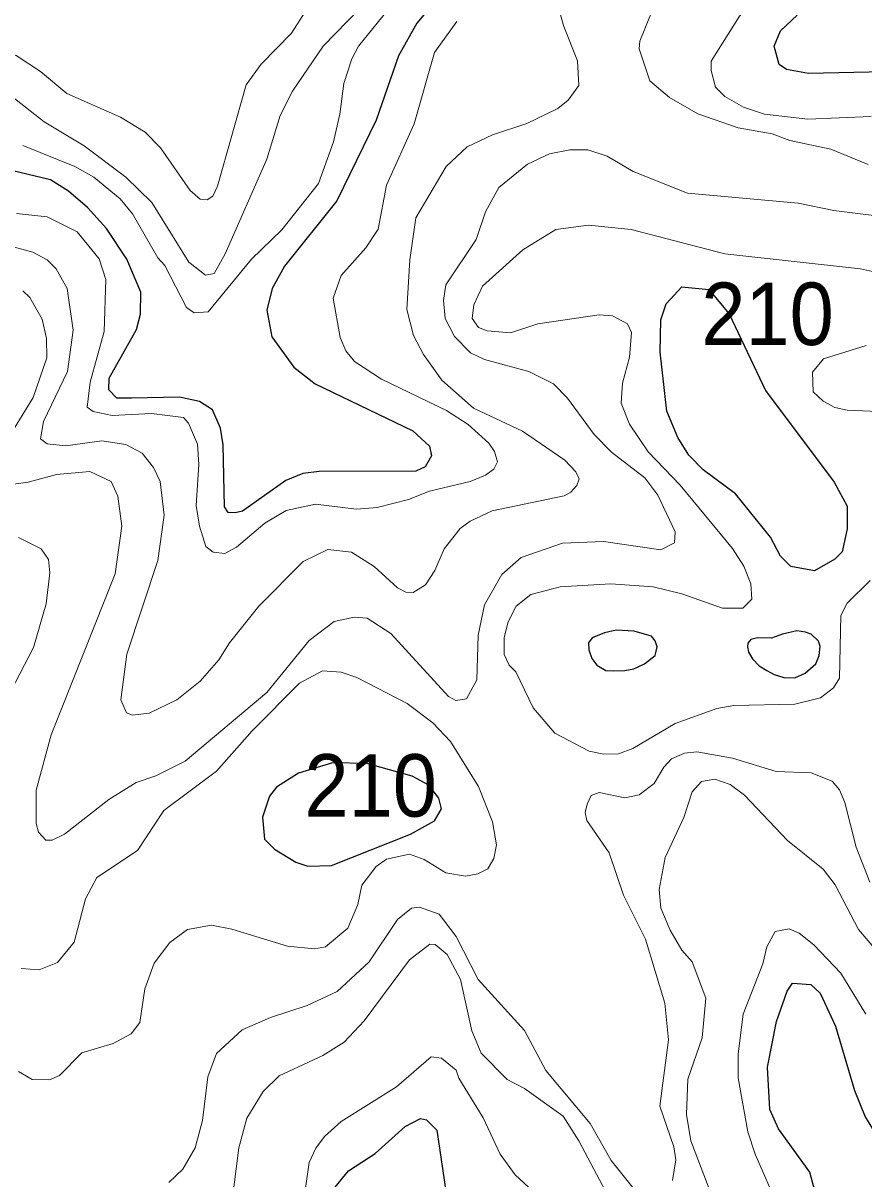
# Model space of a CAD drawing. Extents: x 673.6 to 698.9, y 7012 to 7040.1.
# Drawn here: x 694.799 to 695.876, y 7018.541 to 7020.022 of the extents above; entities that cross this region are included whole.
import ezdxf

# ---------------------------------------------------------------- set-up
doc = ezdxf.new("R2010")
doc.units = 0
doc.header["$LTSCALE"] = 0.032
doc.layers.add('1', color=7, linetype='Continuous', lineweight=25)
doc.layers.add('2', color=7, linetype='Continuous', lineweight=13)
doc.layers.add('21', color=7, linetype='Continuous')

msp = doc.modelspace()

# ---------------------------------------------------------------- linework, layer by layer
at = {"layer": '1'}
for points in [[(695.3336, 7020.0584), (695.3035, 7020.0216), (695.28, 7019.9796), (695.2513, 7019.8974), (695.2012, 7019.7939), (695.1342, 7019.7102), (695.1181, 7019.6817), (695.1115, 7019.654), (695.1177, 7019.6201), (695.1462, 7019.5812), (695.1734, 7019.5599), (695.2985, 7019.4995), (695.3197, 7019.48), (695.3223, 7019.4673), (695.3142, 7019.4535), (695.3024, 7019.448), (695.1784, 7019.4475), (695.1576, 7019.445), (695.1358, 7019.4358), (695.0801, 7019.3967), (695.0707, 7019.3943), (695.0619, 7019.3949), (695.0572, 7019.4023), (695.0555, 7019.4816), (695.0521, 7019.503), (695.042, 7019.5266), (695.0251, 7019.5371), (694.9997, 7019.5428), (694.9381, 7019.5412), (694.9192, 7019.5415), (694.9093, 7019.5522), (694.9094, 7019.5668), (694.9447, 7019.6295), (694.9495, 7019.6488), (694.9502, 7019.6769), (694.9323, 7019.7195), (694.9063, 7019.7586), (694.8819, 7019.7855), (694.8575, 7019.8066), (694.8347, 7019.8208), (694.7757, 7019.8349)], [(695.9796, 7019.9611), (695.805, 7019.9573), (695.7767, 7019.9622), (695.7673, 7019.9688), (695.7608, 7019.9923), (695.7689, 7020.012), (695.7903, 7020.032)], [(695.8148, 7018.5198), (695.8066, 7018.5501), (695.7663, 7018.6056), (695.7554, 7018.6302), (695.7525, 7018.6845), (695.7639, 7018.743), (695.7776, 7018.7819), (695.7846, 7018.7923), (695.8081, 7018.7905), (695.8199, 7018.7791), (695.8394, 7018.7371)], [(695.8394, 7018.7371), (695.8638, 7018.6546), (695.8776, 7018.6208), (695.9162, 7018.5575), (695.9674, 7018.4879), (696.038, 7018.4132)], [(695.1951, 7018.5261), (695.2158, 7018.5518), (695.25, 7018.5738), (695.2884, 7018.6086), (695.3081, 7018.6189), (695.3158, 7018.617), (695.3289, 7018.604), (695.3407, 7018.5258)]]:
    msp.add_lwpolyline(points, dxfattribs=at)
for points in [[(695.7032, 7019.6495), (695.7497, 7019.5513), (695.8376, 7019.4338), (695.8542, 7019.4031), (695.8543, 7019.374), (695.848, 7019.3447), (695.8387, 7019.3352), (695.8127, 7019.3203), (695.7824, 7019.3259), (695.7691, 7019.3388), (695.7563, 7019.3633), (695.7113, 7019.4187), (695.67, 7019.4497), (695.6519, 7019.4684), (695.6375, 7019.4909), (695.6234, 7019.5247), (695.6151, 7019.6003), (695.616, 7019.6415), (695.6228, 7019.6623), (695.6429, 7019.684), (695.6771, 7019.6805)], [(695.5588, 7019.2441), (695.5437, 7019.2408), (695.5278, 7019.2343), (695.5233, 7019.2278), (695.5237, 7019.2192), (695.5274, 7019.2078), (695.5339, 7019.1996), (695.5454, 7019.1927), (695.5556, 7019.1923), (695.5699, 7019.1927), (695.5813, 7019.1947), (695.5951, 7019.2009), (695.6086, 7019.2119), (695.6111, 7019.2229), (695.6086, 7019.2306), (695.6041, 7019.2364), (695.5951, 7019.2392), (695.5817, 7019.2429)], [(695.7575, 7019.2339), (695.7396, 7019.2343), (695.731, 7019.2323), (695.7273, 7019.2274), (695.7269, 7019.2229), (695.7282, 7019.216), (695.7331, 7019.2074), (695.7416, 7019.1984), (695.7514, 7019.1927), (695.7608, 7019.1874), (695.7734, 7019.1837), (695.7873, 7019.1833), (695.8008, 7019.189), (695.8142, 7019.2013), (695.8187, 7019.2119), (695.82, 7019.2237), (695.8179, 7019.2302), (695.8085, 7019.2392), (695.8012, 7019.2417), (695.7898, 7019.2433), (695.7718, 7019.2392)], [(695.164, 7018.9419), (695.1941, 7018.9428), (695.2953, 7018.9829), (695.3259, 7018.9999), (695.3351, 7019.0155), (695.3318, 7019.0292), (695.3188, 7019.0455), (695.2976, 7019.0573), (695.2396, 7019.0736), (695.1954, 7019.0744), (695.1522, 7019.0611), (695.1238, 7019.0431), (695.1148, 7019.0317), (695.1058, 7019.0046), (695.1085, 7018.9764), (695.1211, 7018.9638), (695.1485, 7018.9471)]]:
    msp.add_lwpolyline(points, close=True, dxfattribs=at)
at = {"layer": '2'}
for points in [[(695.6859, 7019.9398), (695.6802, 7019.9608), (695.6803, 7019.9731), (695.7164, 7020.0304), (695.7511, 7020.0724), (695.788, 7020.1045)], [(695.2609, 7020.0722), (695.1834, 7019.9921), (695.1442, 7019.9345), (695.1286, 7019.9033), (695.1113, 7019.8474), (695.0582, 7019.7264), (695.044, 7019.7009), (695.0328, 7019.6989), (695.0117, 7019.7157), (694.9641, 7019.7921), (694.9308, 7019.8244), (694.8778, 7019.8646), (694.8262, 7019.8952), (694.7847, 7019.928)], [(695.4765, 7020.0722), (695.4915, 7020.0174), (695.5091, 7019.9736), (695.5108, 7019.9418), (695.4974, 7019.9231), (695.4842, 7019.9125), (695.4445, 7019.8932), (695.4004, 7019.8788), (695.3679, 7019.8633), (695.341, 7019.8381), (695.3022, 7019.7725), (695.2946, 7019.7184), (695.2907, 7019.6547), (695.2992, 7019.6215), (695.3119, 7019.5974), (695.3355, 7019.5645)], [(694.7048, 7020.0423), (694.7308, 7020.0091), (694.7439, 7019.9984), (694.7907, 7019.9802), (694.8216, 7019.9599), (694.8555, 7019.9316), (694.9241, 7019.9011), (694.9558, 7019.8822)], [(695.2711, 7020.0444), (695.2288, 7019.992), (695.2203, 7019.976), (695.2102, 7019.9445), (695.2051, 7019.9049), (695.1966, 7019.8695), (695.1778, 7019.8163), (695.1306, 7019.7568), (695.0917, 7019.7195), (695.0362, 7019.6518), (695.0183, 7019.6506), (695.0084, 7019.6573), (694.9808, 7019.7113), (694.9721, 7019.7211), (694.9393, 7019.7776), (694.9235, 7019.7965), (694.8901, 7019.8243), (694.8658, 7019.8382), (694.7989, 7019.8651)], [(695.0423, 7019.8001), (695.0483, 7019.813), (695.085, 7019.9425), (695.104, 7019.9693), (695.1429, 7020.009), (695.1607, 7020.0363)], [(695.8811, 7019.8405), (695.8334, 7019.8604), (695.781, 7019.8714), (695.7583, 7019.8799), (695.715, 7019.8875), (695.6631, 7019.9056), (695.6269, 7019.9263), (695.6016, 7019.9478), (695.5881, 7019.9887), (695.5888, 7019.9985), (695.6025, 7020.0321)], [(695.3549, 7020.0239), (695.326, 7019.9841), (695.2999, 7019.8929), (695.2646, 7019.814), (695.254, 7019.7579), (695.2383, 7019.7337), (695.2064, 7019.6984), (695.1962, 7019.6696), (695.2053, 7019.619), (695.2127, 7019.6021), (695.2238, 7019.5884), (695.2583, 7019.5658), (695.3415, 7019.5256), (695.369, 7019.5075), (695.3955, 7019.4839), (695.403, 7019.4731), (695.4068, 7019.46), (695.4022, 7019.4503), (695.3915, 7019.4427), (695.3719, 7019.4347), (695.3198, 7019.4224), (695.293, 7019.4116), (695.2525, 7019.4015), (695.2262, 7019.3991), (695.1736, 7019.4056), (695.1364, 7019.3973), (695.1088, 7019.3814), (695.0725, 7019.3504), (695.0576, 7019.3425), (695.0427, 7019.344), (695.0334, 7019.3515), (695.0252, 7019.3774), (695.0211, 7019.4037), (695.0243, 7019.4566), (695.0227, 7019.4825), (695.011, 7019.5094), (695.0046, 7019.5164), (694.9637, 7019.5216), (694.9134, 7019.5191), (694.8892, 7019.5243), (694.8816, 7019.5298), (694.8854, 7019.5617), (694.9034, 7019.6267), (694.9052, 7019.6932), (694.8967, 7019.7198), (694.8687, 7019.7543), (694.8301, 7019.7738), (694.791, 7019.7778)], [(695.885, 7019.902), (695.8039, 7019.8987), (695.7486, 7019.9052), (695.7215, 7019.9142), (695.698, 7019.9277), (695.6859, 7019.9398)], [(694.9558, 7019.8822), (694.9755, 7019.8619), (695.0131, 7019.8072), (695.026, 7019.7961), (695.0351, 7019.7952), (695.0423, 7019.8001)], [(695.9024, 7019.7738), (695.8374, 7019.7818), (695.7915, 7019.7911), (695.6501, 7019.8039), (695.5806, 7019.8318), (695.5471, 7019.8513), (695.5223, 7019.8592), (695.4993, 7019.8592), (695.4733, 7019.8543), (695.4452, 7019.8411), (695.4084, 7019.811), (695.3915, 7019.78), (695.3795, 7019.7446), (695.3408, 7019.6866), (695.3375, 7019.6665), (695.3397, 7019.6433), (695.3519, 7019.6203), (695.372, 7019.5996), (695.3902, 7019.5908), (695.447, 7019.5756), (695.4785, 7019.5596), (695.4965, 7019.5415), (695.5303, 7019.4947), (695.5529, 7019.4722), (695.5954, 7019.4393), (695.6119, 7019.4171), (695.634, 7019.3701), (695.6332, 7019.3561), (695.616, 7019.3473), (695.5424, 7019.3579), (695.49, 7019.3556), (695.4369, 7019.3374), (695.4122, 7019.3155), (695.3903, 7019.2766), (695.3818, 7019.2377), (695.3801, 7019.1808)], [(695.8945, 7019.702), (695.8715, 7019.7071), (695.6979, 7019.7262), (695.5779, 7019.7574), (695.5233, 7019.7631), (695.4813, 7019.7573), (695.439, 7019.7315), (695.3874, 7019.6848), (695.3763, 7019.6611), (695.3745, 7019.6435), (695.3825, 7019.6319), (695.3934, 7019.6275), (695.4234, 7019.6251), (695.4582, 7019.6365), (695.5371, 7019.648), (695.5538, 7019.6469), (695.573, 7019.6364), (695.5781, 7019.6256), (695.5756, 7019.5939), (695.5668, 7019.5605), (695.565, 7019.535), (695.5756, 7019.5079), (695.5998, 7019.4728), (695.6408, 7019.43), (695.7075, 7019.3488), (695.7222, 7019.3264), (695.7311, 7019.3034), (695.7325, 7019.2839), (695.7209, 7019.2722), (695.6947, 7019.2726), (695.6428, 7019.2906), (695.6061, 7019.2996), (695.5519, 7019.3037), (695.4869, 7019.2997), (695.4494, 7019.2898), (695.4305, 7019.275), (695.4206, 7019.2548), (695.4155, 7019.2347), (695.4154, 7019.213), (695.4219, 7019.1996), (695.4304, 7019.1909), (695.4524, 7019.1446), (695.4802, 7019.1125), (695.524, 7019.0894), (695.543, 7019.0852), (695.5615, 7019.0858), (695.5801, 7019.0927), (695.6342, 7019.1246), (695.6876, 7019.1441), (695.7094, 7019.1476), (695.7873, 7019.1493), (695.8201, 7019.1576), (695.8367, 7019.1703), (695.8444, 7019.1826), (695.8462, 7019.263), (695.8544, 7019.279), (695.8839, 7019.3078)], [(695.3588, 7019.3743), (695.3384, 7019.3484), (695.3264, 7019.3206), (695.3146, 7019.3024), (695.299, 7019.2923), (695.2893, 7019.293), (695.2788, 7019.2986), (695.2487, 7019.3259), (695.2197, 7019.3441), (695.1895, 7019.3474), (695.1581, 7019.3322), (695.1014, 7019.275), (695.0636, 7019.2278), (695.0502, 7019.2061), (695.0263, 7019.1791), (694.9963, 7019.155), (694.9608, 7019.1381), (694.9393, 7019.1353), (694.932, 7019.1383), (694.9245, 7019.1551), (694.9324, 7019.2133), (694.9717, 7019.3334), (694.98, 7019.3914), (694.9749, 7019.4348), (694.9664, 7019.4527), (694.9518, 7019.4708), (694.9309, 7019.4819), (694.9004, 7019.4869), (694.8539, 7019.4805), (694.8302, 7019.4827), (694.8219, 7019.4892), (694.8255, 7019.5113), (694.8561, 7019.5756), (694.8633, 7019.6284), (694.8558, 7019.682), (694.8419, 7019.707), (694.8303, 7019.7185), (694.8119, 7019.7284), (694.7745, 7019.7384)], [(694.7641, 7019.4642), (694.8123, 7019.542), (694.8296, 7019.5931), (694.8295, 7019.6176), (694.8237, 7019.6427), (694.8082, 7019.6702), (694.7992, 7019.6789)], [(695.923, 7019.5232), (695.8542, 7019.5261), (695.8386, 7019.5295), (695.8238, 7019.5375), (695.811, 7019.5493), (695.81, 7019.5748), (695.8241, 7019.5916), (695.8787, 7019.6088)], [(695.3355, 7019.5645), (695.3759, 7019.5285), (695.4389, 7019.4992), (695.493, 7019.4621), (695.5072, 7019.447), (695.5111, 7019.4379)], [(695.2398, 7019.2597), (695.2232, 7019.261), (695.1977, 7019.2555), (695.1655, 7019.2311), (695.1116, 7019.1642), (695.0069, 7019.0766), (694.9694, 7019.0577), (694.9442, 7019.0492), (694.909, 7019.0274), (694.8523, 7018.9831), (694.8366, 7018.9751), (694.8287, 7018.9753), (694.8192, 7018.9856), (694.8162, 7018.9968), (694.8162, 7019.0395), (694.8355, 7019.1101), (694.9173, 7019.3162), (694.9257, 7019.3774), (694.9207, 7019.4159), (694.9122, 7019.4345), (694.8849, 7019.4474), (694.8423, 7019.4435), (694.8061, 7019.4336), (694.7777, 7019.4301)], [(695.5111, 7019.4379), (695.5085, 7019.4294), (695.5006, 7019.4209), (695.492, 7019.4164), (695.4, 7019.3972), (695.3717, 7019.3839), (695.3588, 7019.3743)], [(694.7721, 7019.1439), (694.8126, 7019.2222), (694.8288, 7019.2778), (694.8337, 7019.3176), (694.8319, 7019.3348), (694.8224, 7019.3483), (694.7935, 7019.363)], [(695.3801, 7019.1808), (695.3671, 7019.1564), (695.3534, 7019.1542), (695.344, 7019.1593), (695.2703, 7019.2401), (695.2398, 7019.2597)], [(694.7937, 7018.6791), (694.8109, 7018.6687), (694.8334, 7018.6685), (694.8459, 7018.6737), (694.8748, 7018.703), (694.9149, 7018.7148), (694.9376, 7018.7273), (694.9489, 7018.7417), (694.9554, 7018.7848), (694.967, 7018.8177), (694.9872, 7018.844), (695.0097, 7018.8607), (695.0408, 7018.8664), (695.0666, 7018.8613), (695.1377, 7018.8394), (695.1726, 7018.8362), (695.1866, 7018.8386), (695.2151, 7018.8627), (695.2281, 7018.8928), (695.2331, 7018.9175), (695.2513, 7018.9414), (695.2647, 7018.951), (695.294, 7018.9575), (695.3129, 7018.9503), (695.3405, 7018.9336), (695.3656, 7018.9291), (695.3817, 7018.932), (695.3945, 7018.9386), (695.4021, 7018.9517), (695.4056, 7018.9694), (695.4005, 7018.9987), (695.3826, 7019.044), (695.3464, 7019.1016), (695.3239, 7019.1257), (695.2911, 7019.1502), (695.2265, 7019.1837), (695.2065, 7019.1904), (695.1828, 7019.1921), (695.1532, 7019.1764), (695.0925, 7019.1155), (695.0472, 7019.0636), (694.9797, 7019.0133), (694.9457, 7018.9621), (694.8937, 7018.9273), (694.8791, 7018.9001), (694.8646, 7018.8446), (694.8433, 7018.8186), (694.82, 7018.8093), (694.7971, 7018.8107)], [(695.6307, 7018.5392), (695.6349, 7018.5658), (695.6324, 7018.5826), (695.6144, 7018.6345), (695.6258, 7018.7196), (695.6209, 7018.7663), (695.5963, 7018.8485), (695.5681, 7018.905), (695.5499, 7018.9592), (695.521, 7019.0003), (695.5189, 7019.0109), (695.5215, 7019.0214), (695.5265, 7019.0325), (695.5369, 7019.0365), (695.5697, 7019.0294), (695.5883, 7019.0335), (695.6073, 7019.0477), (695.6199, 7019.0689), (695.6295, 7019.0794), (695.646, 7019.0865), (695.6621, 7019.0884), (695.7077, 7019.0803), (695.7636, 7019.063), (695.8083, 7019.0613), (695.8352, 7019.0508), (695.8445, 7019.0396), (695.8515, 7019.0234), (695.866, 7018.9665), (695.8836, 7018.9215)], [(695.6785, 7018.5264), (695.6543, 7018.5902), (695.6489, 7018.6238), (695.6506, 7018.6692), (695.6687, 7018.7223), (695.6734, 7018.7731), (695.6559, 7018.8196), (695.6426, 7018.8343), (695.6276, 7018.86), (695.616, 7018.8883), (695.6136, 7018.9121), (695.6213, 7018.9532), (695.6455, 7019.0043), (695.6561, 7019.0372), (695.6678, 7019.0505), (695.6851, 7019.0532), (695.7047, 7019.0465), (695.7231, 7019.0331), (695.7781, 7018.9748), (695.8237, 7018.9383), (695.8391, 7018.918), (695.8688, 7018.8607), (695.9059, 7018.8175)], [(694.9859, 7018.5369), (695.0037, 7018.5537), (695.0197, 7018.5813), (695.0291, 7018.6164), (695.0358, 7018.6723), (695.0472, 7018.7019), (695.0797, 7018.7323), (695.1161, 7018.7481), (695.1631, 7018.7633), (695.2016, 7018.7816), (695.2426, 7018.8194), (695.2787, 7018.8736), (695.2967, 7018.8883), (695.307, 7018.8896), (695.3322, 7018.8803), (695.3538, 7018.8517), (695.3818, 7018.7967), (695.4413, 7018.7315), (695.4686, 7018.6802), (695.5255, 7018.6125), (695.5523, 7018.5652), (695.583, 7018.5266)], [(695.7662, 7018.5057), (695.7366, 7018.5729), (695.7271, 7018.6015), (695.7147, 7018.6707), (695.7147, 7018.7016), (695.7211, 7018.7525), (695.7465, 7018.8169), (695.7514, 7018.8387), (695.7621, 7018.8581), (695.7802, 7018.8617), (695.7929, 7018.8562), (695.8117, 7018.841), (695.8461, 7018.8049), (695.8781, 7018.7523)], [(695.0686, 7018.5273), (695.0754, 7018.5811), (695.0858, 7018.6193), (695.1068, 7018.6532), (695.1274, 7018.6736), (695.1832, 7018.6995), (695.2106, 7018.7166), (695.236, 7018.7439), (695.294, 7018.8221), (695.32, 7018.842), (695.3269, 7018.8417), (695.3422, 7018.8287), (695.3593, 7018.7966), (695.3738, 7018.7312), (695.3858, 7018.7023), (695.4191, 7018.6686), (695.4413, 7018.6574), (695.4907, 7018.6218), (695.511, 7018.5901), (695.5529, 7018.5112)], [(695.1741, 7018.5809), (695.1853, 7018.5956), (695.2068, 7018.6151), (695.2774, 7018.6595), (695.322, 7018.6979), (695.3349, 7018.6962), (695.3538, 7018.6805), (695.3571, 7018.6704), (695.3886, 7018.6195), (695.41, 7018.5733), (695.4295, 7018.5466), (695.5033, 7018.4784)], [(695.0839, 7018.4163), (695.1187, 7018.4312), (695.141, 7018.452), (695.1607, 7018.5267), (695.1657, 7018.5625), (695.1741, 7018.5809)]]:
    msp.add_lwpolyline(points, dxfattribs=at)

# ---------------------------------------------------------------- texts
at = {"layer": '21', "width": 0.95}
for p in [(695.6677, 7019.6094), (695.1596, 7019.0054)]:
    msp.add_text('210', height=0.08, dxfattribs=at).set_placement(p)

doc.saveas('drawing.dxf')
